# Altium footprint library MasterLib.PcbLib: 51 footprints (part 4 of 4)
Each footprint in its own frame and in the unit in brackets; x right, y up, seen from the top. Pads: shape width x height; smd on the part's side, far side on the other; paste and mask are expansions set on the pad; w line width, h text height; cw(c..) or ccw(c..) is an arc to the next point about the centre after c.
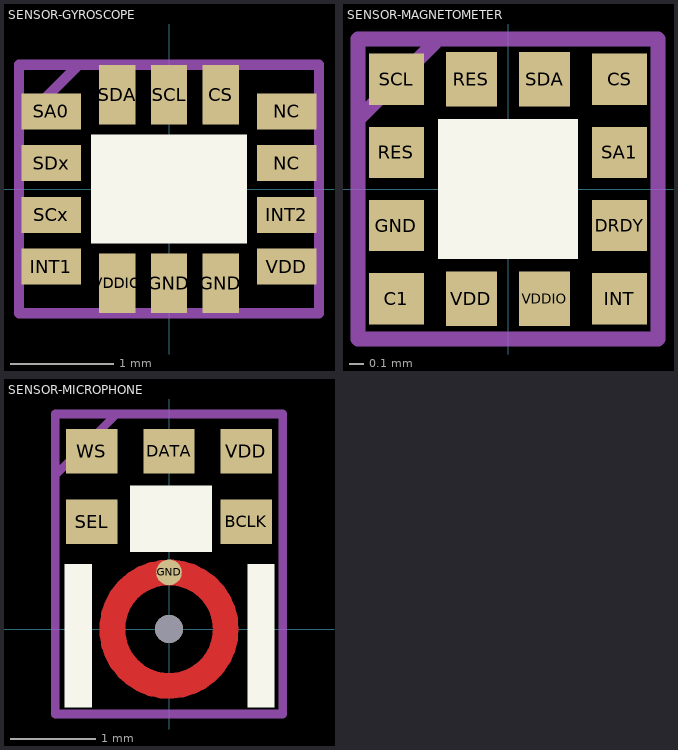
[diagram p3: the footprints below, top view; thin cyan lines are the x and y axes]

## SENSOR-GYROSCOPE [mm]
height 0.86
pads (14):
  rect 0.35x0.575 smd: CS(0.5,0.913) GND(0,-0.913) GND(0.5,-0.913) SCL(0,0.913) SDA(-0.5,0.913) VDDIO(-0.5,-0.913)
  rect 0.575x0.35 smd: INT1(-1.138,-0.75) INT2(1.138,-0.25) NC(1.138,0.25) NC(1.138,0.75) SA0(-1.138,0.75) SCx(-1.138,-0.25) SDx(-1.138,0.25) VDD(1.138,-0.75)
Top Overlay:
  region: -0.75,0.525 0.75,0.525 0.75,-0.525 -0.75,-0.525
Assembly Top:
  lines w0.1: -1.436,0.637 -0.881,1.192 ; -1.45,-1.2 -1.45,1.2 1.45,1.2 1.45,-1.2 -1.45,-1.2
  text ".Designator" at -0.6,-0.2 h0.4
3D body "SENSOR-GYROSCOPE.step": height 0.75, standoff -0.11, extent -1.504,-1.254 1.496,1.246

## SENSOR-MAGNETOMETER [mm]
height 1
pads (12):
  rect 0.375x0.35 smd: C1(-0.763,-0.75) CS(0.763,0.75) DRDY(0.763,-0.25) GND(-0.763,-0.25) INT(0.763,-0.75) RES(-0.763,0.25) SA1(0.763,0.25) SCL(-0.763,0.75)
  rect 0.35x0.375 smd: RES(-0.25,0.75) SDA(0.25,0.75) VDD(-0.25,-0.75) VDDIO(0.25,-0.75)
Top Overlay:
  region: -0.475,0.475 0.475,0.475 0.475,-0.475 -0.475,-0.475
Assembly Top:
  lines w0.1: -1.016,0.484 -0.5,1 ; -1.025,-1.025 -1.025,1.025 1.025,1.025 1.025,-1.025 -1.025,-1.025
  text ".Designator" at -0.6,-0.2 h0.4
3D body "SENSOR-MAGNETOMETER.step": height 0.91, standoff -0.07, extent -0.999,-1.001 1.001,0.999

## SENSOR-MICROPHONE [mm]
height 1.08
pads (6):
  rect 0.6x0.522 smd: BCLK(0.9,1.252) DATA(0,2.074) SEL(-0.9,1.252) VDD(0.9,2.074) WS(-0.9,2.074)
  round 0.3 smd paste+0 mask+0: GND(0,0.662)
via 0,0 diameter 0.325 hole 0.325
Top Layer:
  circle w0.3: c0,0 r0.662
Top Overlay:
  rectangle: 0.914,-0.914 1.234,0.762
  rectangle: -1.219,-0.914 -0.9,0.762
  rectangle: -0.457,0.9 0.5,1.676
Assembly Top:
  lines w0.1: -1.325,1.8 -0.625,2.5 ; -1.325,-0.99 -1.325,2.51 1.325,2.51 1.325,-0.99 -1.325,-0.99
  text ".Designator" at 0.2,0 h0.4
3D body "SENSOR-MICROPHONE.step": height 0.94, standoff -0.09, extent -1.325,-1 1.325,2.5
